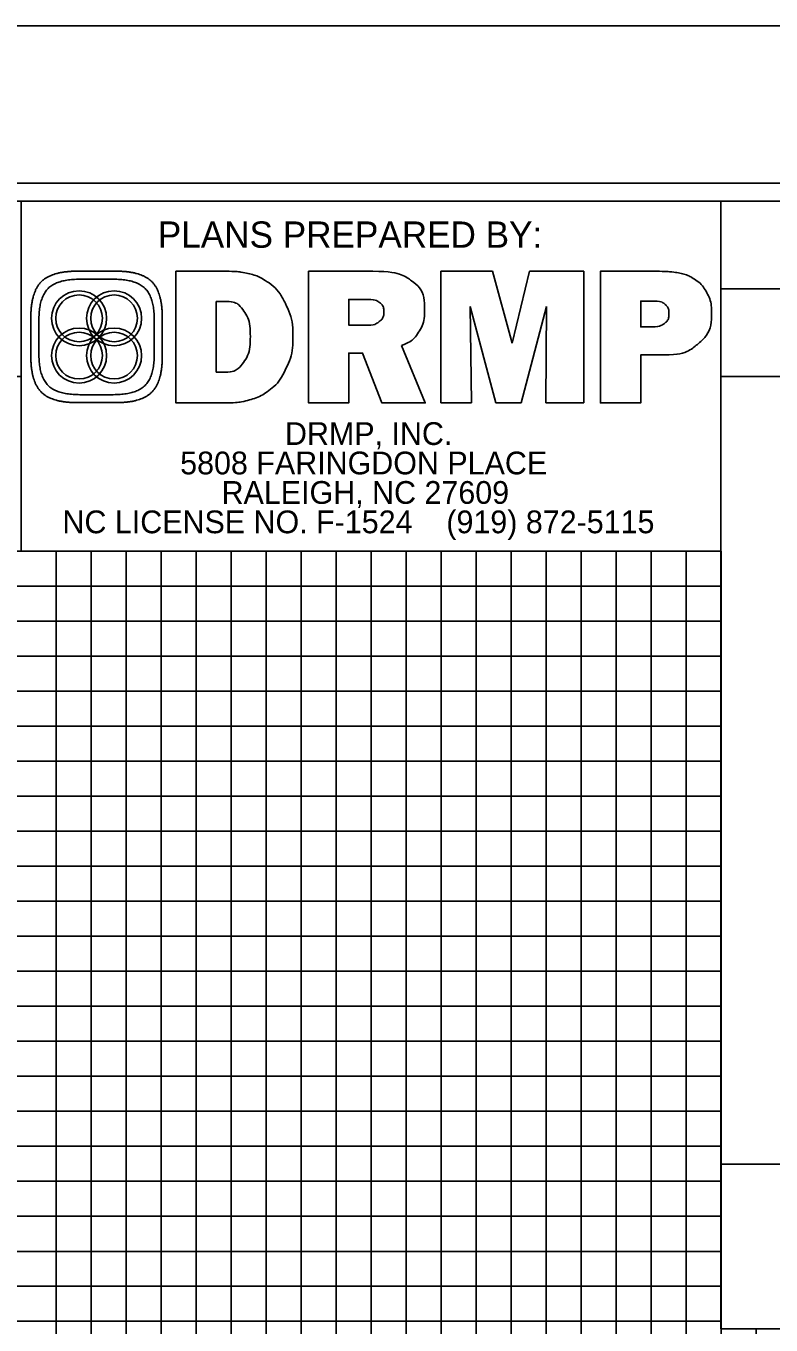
# Model space of a CAD drawing. Extents: x 1260839 to 1262605, y 747346 to 748446.
# Drawn here: x 1262206.4 to 1262312.9, y 748260.2 to 748445.7 of the extents above; entities that cross this region are included whole.
import ezdxf

# ---------------------------------------------------------------- set-up
doc = ezdxf.new("R2010")
doc.units = 0
for name, color, linetype in [('Pattern 1', 7, 'Continuous'), ('Pattern 2', 7, 'Continuous'), ('Prop Drainage Structure Bridge Opening', 7, 'Continuous'), ('Prop Grid Mask', 7, 'Continuous'), ('Prop Horizontal Alignment', 7, 'Continuous'), ('Prop Paved Shoulder', 7, 'Continuous'), ('Prop PFL Text', 7, 'Continuous'), ('Prop Terminator CELL', 7, 'Continuous'), ('Prop VPI Label', 7, 'Continuous'), ('Sheet Block System Information CELL', 7, 'Continuous'), ('Sheet Layout Plan Border', 7, 'Continuous'), ('Sheet Project Info Box CELL', 7, 'Continuous'), ('Sheet Sticker Exception Certification CELL', 7, 'Continuous')]:
    doc.layers.add(name, color=color, linetype=linetype)

msp = doc.modelspace()

# ---------------------------------------------------------------- linework, layer by layer
at = {"layer": 'Pattern 1'}
for points in [[(1262305.7, 748345.74), (1261005.85, 748345.74), (1261005.85, 748395.69), (1262205.75, 748395.69)], [(1262255.75, 748370.74), (1262255.75, 747395.74), (1262305.75, 747395.74), (1262305.75, 748370.74)], [(1262505.75, 748245.74), (1261005.75, 748245.74), (1261005.75, 748295.74), (1262305.7, 748295.74)]]:
    msp.add_lwpolyline(points, dxfattribs=at)
at = {"layer": 'Pattern 2'}
for points in [[(1261005.75, 748370.74), (1262305.7, 748370.74)], [(1262230.75, 748370.74), (1262230.75, 747395.74), (1262280.75, 747395.74), (1262280.75, 748370.74)], [(1262305.7, 748320.74), (1261005.75, 748320.74), (1261005.75, 748270.69), (1262305.7, 748270.69)]]:
    msp.add_lwpolyline(points, dxfattribs=at)
at = {"layer": 'Prop Drainage Structure Bridge Opening'}
msp.add_line((1262522.75, 748445.74), (1260838.75, 748445.74), dxfattribs=at)
at = {"layer": 'Prop Grid Mask'}
msp.add_lwpolyline([(1262455.75, 748259.69), (1262455.75, 747395.74), (1261055.75, 747395.74), (1261055.75, 748420.74), (1262305.7, 748420.74), (1262305.7, 748259.69)], close=True, dxfattribs=at)
at = {"layer": 'Prop Horizontal Alignment'}
msp.add_lwpolyline([(1262305.7, 748420.74), (1262305.7, 748370.74), (1262205.75, 748370.74), (1262205.75, 748420.74)], close=True, dxfattribs=at)
at = {"layer": 'Prop Paved Shoulder'}
msp.add_line((1262305.7, 748408.19), (1262505.75, 748408.19), dxfattribs=at)
for points in [[(1262505.75, 748420.74), (1261005.75, 748420.74), (1261005.75, 747370.74), (1262505.75, 747370.74)], [(1262305.7, 748420.74), (1262505.75, 748420.74), (1262505.75, 748395.69), (1262305.7, 748395.69)], [(1262305.7, 748395.69), (1262405.75, 748395.69), (1262405.75, 748283.19), (1262305.7, 748283.19)]]:
    msp.add_lwpolyline(points, close=True, dxfattribs=at)
at = {"layer": 'Prop PFL Text'}
for p, q in [((1262255.75, 748370.74), (1262255.75, 747395.74)), ((1261005.75, 748345.74), (1262305.7, 748345.74)), ((1261005.75, 748295.74), (1262305.7, 748295.74)), ((1262305.75, 747395.74), (1262305.75, 748283.19))]:
    msp.add_line(p, q, dxfattribs=at)
at = {"layer": 'Prop Terminator CELL'}
msp.add_lwpolyline([(1262518.25, 748423.29), (1260851.75, 748423.29), (1260851.75, 747368.19), (1262518.25, 747368.19)], close=True, dxfattribs=at)
at = {"layer": 'Prop VPI Label'}
msp.add_lwpolyline([(1262522.75, 748445.74), (1260838.75, 748445.74), (1260838.75, 747345.74), (1262522.75, 747345.74)], close=True, dxfattribs=at)
at = {"layer": 'Sheet Block System Information CELL'}
for centre, radius in [((1262214.03, 748403.99), 3.93), ((1262219.03, 748403.99), 3.93), ((1262214.03, 748403.99), 3.34), ((1262219.03, 748403.99), 3.34), ((1262214.03, 748398.66), 3.93), ((1262219.03, 748398.66), 3.93), ((1262214.03, 748398.66), 3.34), ((1262219.03, 748398.66), 3.34)]:
    msp.add_circle(centre, radius, dxfattribs=at)
at = {"layer": 'Sheet Layout Plan Border'}
for p, q in [((1262305.7, 748259.69), (1262305.7, 748283.19)), ((1262305.7, 748283.19), (1262505.74, 748283.19))]:
    msp.add_line(p, q, dxfattribs=at)
at = {"layer": 'Sheet Project Info Box CELL'}
for p, q in [((1262213.81, 748410.72), (1262219.26, 748410.72)), ((1262265.69, 748391.9), (1262265.69, 748410.7)), ((1262265.69, 748410.7), (1262273.08, 748410.7)), ((1262273.08, 748410.7), (1262275.9, 748400.43)), ((1262275.9, 748400.43), (1262278.38, 748410.7)), ((1262278.38, 748410.7), (1262286.1, 748410.7)), ((1262286.1, 748410.7), (1262286.1, 748391.9)), ((1262218.92, 748409.57), (1262214.14, 748409.57)), ((1262273.54, 748391.9), (1262269.89, 748405.69)), ((1262269.89, 748405.69), (1262270.08, 748391.9)), ((1262280.77, 748405.69), (1262277.19, 748391.9)), ((1262280.68, 748391.9), (1262280.77, 748405.69)), ((1262207.14, 748398.6), (1262207.14, 748404.05)), ((1262208.29, 748403.72), (1262208.29, 748398.94)), ((1262224.77, 748398.94), (1262224.77, 748403.72)), ((1262225.92, 748404.05), (1262225.92, 748398.6)), ((1262214.14, 748393.08), (1262218.92, 748393.08)), ((1262219.26, 748391.94), (1262213.81, 748391.94)), ((1262270.08, 748391.9), (1262265.69, 748391.9)), ((1262277.19, 748391.9), (1262273.54, 748391.9)), ((1262286.1, 748391.9), (1262280.68, 748391.9))]:
    msp.add_line(p, q, dxfattribs=at)
for points in [[(1262234.84, 748391.9), (1262227.86, 748391.9), (1262227.86, 748410.7), (1262235.09, 748410.7)], [(1262260.08, 748400.12), (1262263.47, 748391.9), (1262257.29, 748391.9), (1262254.51, 748399.03), (1262252.54, 748399.03), (1262252.54, 748391.9), (1262246.82, 748391.9), (1262246.82, 748410.7), (1262256, 748410.7)], [(1262297.59, 748398.75), (1262294.25, 748398.75), (1262294.25, 748391.9), (1262288.49, 748391.9), (1262288.49, 748410.7), (1262296.5, 748410.7)], [(1262235.09, 748406.38), (1262233.62, 748406.38), (1262233.62, 748396.3), (1262234.92, 748396.3)], [(1262255.19, 748406.69), (1262252.54, 748406.69), (1262252.54, 748403.01), (1262255.27, 748403.01)], [(1262296.15, 748406.45), (1262294.25, 748406.45), (1262294.25, 748402.76), (1262295.8, 748402.76)]]:
    msp.add_lwpolyline(points, dxfattribs=at)
for points, degree in [([(1262207.14, 748404.05), (1262207.14, 748407.72), (1262210.14, 748410.72), (1262213.81, 748410.72)], 2), ([(1262219.26, 748410.72), (1262222.92, 748410.72), (1262225.92, 748407.72), (1262225.92, 748404.05)], 2), ([(1262235.09, 748410.7), (1262236.23, 748410.7), (1262237.25, 748410.6), (1262238.15, 748410.39), (1262239.05, 748410.19), (1262239.83, 748409.88), (1262240.51, 748409.45), (1262241.79, 748408.64), (1262242.79, 748407.53), (1262243.5, 748406.1), (1262244.21, 748404.68), (1262244.57, 748403.08), (1262244.57, 748401.31), (1262244.57, 748399.74), (1262244.26, 748398.27), (1262243.63, 748396.9), (1262243, 748395.54), (1262242.15, 748394.45), (1262241.07, 748393.64), (1262240.27, 748393.05), (1262239.36, 748392.61), (1262238.35, 748392.33), (1262237.34, 748392.05), (1262236.17, 748391.9), (1262234.84, 748391.9)], 3), ([(1262256, 748410.7), (1262258.46, 748410.7), (1262260.3, 748410.24), (1262261.53, 748409.33), (1262262.75, 748408.42), (1262263.36, 748407.04), (1262263.36, 748405.21), (1262263.36, 748403.94), (1262263.08, 748402.87), (1262262.52, 748401.99), (1262261.96, 748401.12), (1262261.15, 748400.49), (1262260.08, 748400.12)], 3), ([(1262296.5, 748410.7), (1262297.76, 748410.7), (1262298.8, 748410.62), (1262299.62, 748410.47), (1262300.44, 748410.31), (1262301.13, 748410.07), (1262301.68, 748409.73), (1262302.56, 748409.18), (1262303.23, 748408.48), (1262303.68, 748407.63), (1262304.14, 748406.78), (1262304.36, 748405.82), (1262304.36, 748404.74), (1262304.36, 748402.95), (1262303.74, 748401.51), (1262302.5, 748400.41), (1262301.25, 748399.3), (1262299.62, 748398.75), (1262297.59, 748398.75)], 3), ([(1262214.14, 748409.57), (1262210.92, 748409.57), (1262208.29, 748406.93), (1262208.29, 748403.72)], 2), ([(1262224.77, 748403.72), (1262224.77, 748406.93), (1262222.14, 748409.57), (1262218.92, 748409.57)], 2), ([(1262234.92, 748396.3), (1262236, 748396.3), (1262236.86, 748396.76), (1262237.51, 748397.69), (1262238.16, 748398.61), (1262238.49, 748399.85), (1262238.49, 748401.39), (1262238.49, 748402.92), (1262238.18, 748404.13), (1262237.56, 748405.03), (1262236.95, 748405.93), (1262236.13, 748406.38), (1262235.09, 748406.38)], 3), ([(1262255.27, 748403.01), (1262255.94, 748403.01), (1262256.49, 748403.18), (1262256.91, 748403.53), (1262257.33, 748403.87), (1262257.55, 748404.31), (1262257.55, 748404.85), (1262257.55, 748405.47), (1262257.35, 748405.93), (1262256.96, 748406.23), (1262256.57, 748406.53), (1262255.98, 748406.69), (1262255.19, 748406.69)], 3), ([(1262295.8, 748402.76), (1262296.58, 748402.76), (1262297.18, 748402.93), (1262297.62, 748403.25), (1262298.05, 748403.58), (1262298.27, 748404.03), (1262298.27, 748404.61), (1262298.27, 748405.2), (1262298.08, 748405.66), (1262297.72, 748405.98), (1262297.36, 748406.29), (1262296.84, 748406.45), (1262296.15, 748406.45)], 3), ([(1262213.81, 748391.94), (1262210.14, 748391.94), (1262207.14, 748394.94), (1262207.14, 748398.6)], 2), ([(1262208.29, 748398.94), (1262208.29, 748395.72), (1262210.92, 748393.08), (1262214.14, 748393.08)], 2), ([(1262218.92, 748393.08), (1262222.14, 748393.08), (1262224.77, 748395.72), (1262224.77, 748398.94)], 2), ([(1262225.92, 748398.6), (1262225.92, 748394.94), (1262222.92, 748391.94), (1262219.26, 748391.94)], 2)]:
    msp.add_open_spline(points, degree=degree, dxfattribs=at)
at = {"layer": 'Sheet Sticker Exception Certification CELL'}
for points in [[(1262210.75, 747395.74), (1262210.75, 748370.74)], [(1262215.75, 748370.74), (1262215.75, 747395.74), (1262220.75, 747395.74), (1262220.75, 748370.74)], [(1262225.75, 748370.74), (1262225.75, 747395.74), (1262235.75, 747395.74), (1262235.75, 748370.74)], [(1262240.75, 748370.74), (1262240.75, 747395.74), (1262245.75, 747395.74), (1262245.75, 748370.74)], [(1262250.75, 748370.74), (1262250.75, 747395.74), (1262260.75, 747395.74), (1262260.75, 748370.74)], [(1262265.75, 748370.74), (1262265.75, 747395.74), (1262270.75, 747395.74), (1262270.75, 748370.74)], [(1262275.75, 748370.74), (1262275.75, 747395.74), (1262285.75, 747395.74), (1262285.75, 748370.74)], [(1262290.75, 748370.74), (1262290.75, 747395.74), (1262295.75, 747395.74), (1262295.75, 748370.74)], [(1262300.75, 748370.74), (1262300.75, 747395.74), (1262310.75, 747395.74), (1262310.75, 748259.69)], [(1262305.7, 748365.74), (1261055.75, 748365.74), (1261055.75, 748360.74), (1262305.7, 748360.74)], [(1262305.7, 748355.74), (1261055.75, 748355.74), (1261055.75, 748350.74), (1262305.7, 748350.74)], [(1262305.7, 748340.74), (1261055.75, 748340.74), (1261055.75, 748335.74), (1262305.7, 748335.74)], [(1262305.7, 748330.74), (1261055.75, 748330.74), (1261055.75, 748325.74), (1262305.7, 748325.74)], [(1262305.7, 748315.74), (1261055.75, 748315.74), (1261055.75, 748310.74), (1262305.7, 748310.74)], [(1262305.7, 748305.74), (1261055.75, 748305.74), (1261055.75, 748300.74), (1262305.7, 748300.74)], [(1262305.7, 748290.74), (1261055.75, 748290.74), (1261055.75, 748285.74), (1262305.7, 748285.74)], [(1262305.7, 748280.74), (1261055.75, 748280.74), (1261055.75, 748280.74), (1261055.75, 748260.74), (1262305.7, 748260.74)], [(1261055.75, 748275.74), (1262305.7, 748275.74)], [(1262305.7, 748265.74), (1261055.75, 748265.74)]]:
    msp.add_lwpolyline(points, dxfattribs=at)

# ---------------------------------------------------------------- texts
at = {"layer": 'Sheet Block System Information CELL'}
msp.add_text('PLANS PREPARED BY:', height=3.75, rotation=360, dxfattribs=at).set_placement((1262225.28, 748414.07))
for s, p in [('DRMP, INC.', (1262243.44, 748385.9)), ('5808 FARINGDON PLACE', (1262228.47, 748381.7)), ('RALEIGH, NC 27609', (1262234.38, 748377.49)), ('NC LICENSE NO. F-1524    (919) 872-5115', (1262211.66, 748373.29))]:
    msp.add_text(s, height=3.25, dxfattribs=at).set_placement(p)

doc.saveas('drawing.dxf')
